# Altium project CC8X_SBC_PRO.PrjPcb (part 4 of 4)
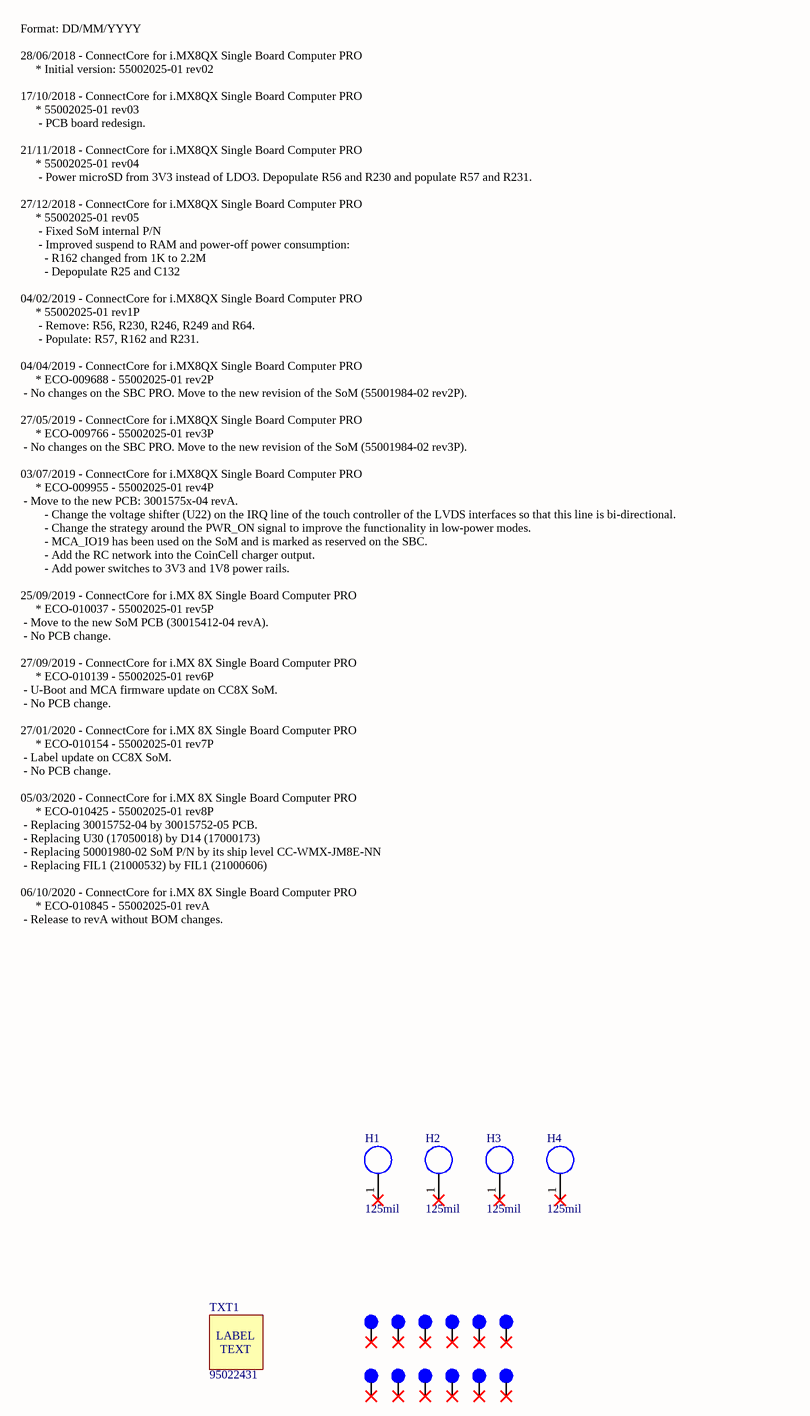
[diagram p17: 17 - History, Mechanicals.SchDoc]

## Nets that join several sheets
1V8_EXT: 02 - CCIMX8X Power, Control, MCA (R3.1 R5.1 R6.1), 03 - CCIMX8X Digital interfaces (R183.2 R184.2), 07 - Console, UART, CAN (C40.2 U10.7 U10.10), 08 - Ethernet1 (5 pins), 09 - Ethernet2 (R106.2 U9.5), 13 - Audio (R193.1 R194.1 R199.1 U21.S), 15 - Expansion connectors, User LEDs, RF signals (J20.4)
3V3_ETH: 08 - Ethernet1 (13 pins), 09 - Ethernet2 (7 pins)
3V3_EXT: 02 - CCIMX8X Power, Control, MCA (R2.1 R257.1), 03 - CCIMX8X Digital interfaces (R179.2 R180.2 R181.2 R182.2), 05 - Power, bootstrap, reset (J2.1 R40.1 R42.2), 06 - JTAG, SWD, MicroSD, Mini PCIe, MicroSIM (R29.1 R46.1 R57.2), 07 - Console, UART, CAN (15 pins), 08 - Ethernet1 (5 pins), 09 - Ethernet2 (R80.1), 10 - Displays and cameras (10 pins), 11 - USB HUB (R144.1 R145.1 R146.1 U24.S), 12 - USB Type C, USB microAB (8 pins), 13 - Audio (5 pins), 14 - I2C, XBee (L22.1 R171.2 R172.2 R196.2), 15 - Expansion connectors, User LEDs, RF signals (J27.1 R203.2 R204.2)
3V3_RF: 02 - CCIMX8X Power, Control, MCA (U1.F17 U1.F18), 04 - CCIMX8X RF, PCIe (R10.2), 15 - Expansion connectors, User LEDs, RF signals (J20.15)
5V: 05 - Power, bootstrap, reset (J3.1 R41.2), 07 - Console, UART, CAN (C145.2 C146.2 R245.1 R248.1), 10 - Displays and cameras (L8.1 L36.1), 15 - Expansion connectors, User LEDs, RF signals (J27.40)
GND: 02 - CCIMX8X Power, Control, MCA (179 pins), 05 - Power, bootstrap, reset (36 pins), 06 - JTAG, SWD, MicroSD, Mini PCIe, MicroSIM (68 pins), 07 - Console, UART, CAN (23 pins), 08 - Ethernet1 (37 pins), 09 - Ethernet2 (31 pins), 10 - Displays and cameras (17 pins), 11 - USB HUB (34 pins), 12 - USB Type C, USB microAB (38 pins), 13 - Audio (32 pins), 14 - I2C, XBee (6 pins), 15 - Expansion connectors, User LEDs, RF signals (8 pins)
LDO3: 02 - CCIMX8X Power, Control, MCA (R221.1), 06 - JTAG, SWD, MicroSD, Mini PCIe, MicroSIM (R56.2)
PCIe_VCC: 06 - JTAG, SWD, MicroSD, Mini PCIe, MicroSIM (26 pins), 14 - I2C, XBee (L23.1)
SHLD: 08 - Ethernet1 (J12.SHLD1 J12.SHLD2 R85.2), 09 - Ethernet2 (J13.SHLD1 J13.SHLD2), 11 - USB HUB (J18.SH1 J18.SH2 J18.SH3 J18.SH4), 12 - USB Type C, USB microAB (J28.6 J28.7 J28.8 J28.9)
VCC_LICELL: 02 - CCIMX8X Power, Control, MCA (D13.K), 05 - Power, bootstrap, reset (D4.1 R18.1), 15 - Expansion connectors, User LEDs, RF signals (J27.38)
VCC_MCA: 02 - CCIMX8X Power, Control, MCA (C162.2 R259.2 R260.2 U1.AM21), 05 - Power, bootstrap, reset (5 pins), 06 - JTAG, SWD, MicroSD, Mini PCIe, MicroSIM (CAD2.1 CAD2.5 J9.1), 15 - Expansion connectors, User LEDs, RF signals (J20.1)
VCC_SCU_1V8: 02 - CCIMX8X Power, Control, MCA (U1.AA29), 05 - Power, bootstrap, reset (R32.2 R35.2 R36.1 R38.1), 06 - JTAG, SWD, MicroSD, Mini PCIe, MicroSIM (CAD1.1 R14.1 R51.2)
VIN_PROT: 02 - CCIMX8X Power, Control, MCA (R1.1), 05 - Power, bootstrap, reset (13 pins), 06 - JTAG, SWD, MicroSD, Mini PCIe, MicroSIM (7 pins), 11 - USB HUB (C84.1 U14.7), 12 - USB Type C, USB microAB (8 pins), 14 - I2C, XBee (R190.1)
VLDO4_1V5: 02 - CCIMX8X Power, Control, MCA (R205.1), 06 - JTAG, SWD, MicroSD, Mini PCIe, MicroSIM (J7.6 J7.28 J7.48)
VSYS: 02 - CCIMX8X Power, Control, MCA (5 pins), 03 - CCIMX8X Digital interfaces (U1.B6)
5V_SBC_PWR_ON: 03 - CCIMX8X Digital interfaces (U1.E28), 05 - Power, bootstrap, reset (R40.2 U2.4)
ADC_IN0: 02 - CCIMX8X Power, Control, MCA (U1.K29), 15 - Expansion connectors, User LEDs, RF signals (J27.25)
ADC_IN1: 02 - CCIMX8X Power, Control, MCA (U1.L29), 15 - Expansion connectors, User LEDs, RF signals (J27.27)
ADC_IN4: 02 - CCIMX8X Power, Control, MCA (U1.AG25), 15 - Expansion connectors, User LEDs, RF signals (J27.26)
ADC_IN5: 02 - CCIMX8X Power, Control, MCA (U1.AG28), 15 - Expansion connectors, User LEDs, RF signals (J27.28)
AUD_I2C_SCL: 13 - Audio (U20.51), 14 - I2C, XBee (R175.2)
AUD_I2C_SDA: 13 - Audio (U20.52), 14 - I2C, XBee (R176.2)
AUD_INT#: 03 - CCIMX8X Digital interfaces (U1.AG15), 13 - Audio (R154.2 U20.56)
AUD_PWR_EN: 03 - CCIMX8X Digital interfaces (U1.E27), 13 - Audio (Q5.G Q6.G R168.2 R194.2)
BT_WAKEUP_HOST: 02 - CCIMX8X Power, Control, MCA (U1.AM25), 04 - CCIMX8X RF, PCIe (U1.G17), 15 - Expansion connectors, User LEDs, RF signals (J20.17)
BT_WAKEUP_SLAVE: 04 - CCIMX8X RF, PCIe (U1.G12), 15 - Expansion connectors, User LEDs, RF signals (J20.18)
CAN1_H: 07 - Console, UART, CAN (R60.2 U6.7), 15 - Expansion connectors, User LEDs, RF signals (J27.11)
CAN1_L: 07 - Console, UART, CAN (R60.1 U6.6), 15 - Expansion connectors, User LEDs, RF signals (J27.9)
CAN1_MODE: 03 - CCIMX8X Digital interfaces (U1.C17), 07 - Console, UART, CAN (R11.1), 15 - Expansion connectors, User LEDs, RF signals (J27.29)
CAN2_H: 07 - Console, UART, CAN (R62.2 U7.7), 15 - Expansion connectors, User LEDs, RF signals (J27.12)
CAN2_L: 07 - Console, UART, CAN (R62.1 U7.6), 15 - Expansion connectors, User LEDs, RF signals (J27.10)
CAN2_MODE: 03 - CCIMX8X Digital interfaces (U1.C18), 07 - Console, UART, CAN (R233.1), 15 - Expansion connectors, User LEDs, RF signals (J27.31)
CAN/RS485#: 03 - CCIMX8X Digital interfaces (U1.AG13), 07 - Console, UART, CAN (R163.1 U4.6 U5.6)
CONSOLE_RX: 03 - CCIMX8X Digital interfaces (U1.V29), 07 - Console, UART, CAN (D6.2 J11.2)
CONSOLE_TX: 03 - CCIMX8X Digital interfaces (U1.W29), 07 - Console, UART, CAN (D7.2 J11.1)
CSI_D00: 03 - CCIMX8X Digital interfaces (U1.AH25), 10 - Displays and cameras (J17.2)
CSI_D01: 03 - CCIMX8X Digital interfaces (U1.AH26), 10 - Displays and cameras (J17.3)
CSI_D02: 03 - CCIMX8X Digital interfaces (U1.AJ25), 10 - Displays and cameras (J17.4)
CSI_D03: 03 - CCIMX8X Digital interfaces (U1.AH24), 10 - Displays and cameras (J17.5)
CSI_D04: 03 - CCIMX8X Digital interfaces (U1.AJ23), 10 - Displays and cameras (J17.6)
CSI_D05: 03 - CCIMX8X Digital interfaces (U1.AJ24), 10 - Displays and cameras (J17.7)
CSI_D06: 03 - CCIMX8X Digital interfaces (U1.AH20), 10 - Displays and cameras (J17.8)
CSI_D07: 03 - CCIMX8X Digital interfaces (U1.AJ22), 10 - Displays and cameras (J17.9)
CSI_EN: 03 - CCIMX8X Digital interfaces (U1.AK27), 10 - Displays and cameras (J17.15)
CSI_HSYNC: 03 - CCIMX8X Digital interfaces (U1.AK28), 10 - Displays and cameras (J17.13)
CSI_MCLK: 03 - CCIMX8X Digital interfaces (U1.AJ21), 10 - Displays and cameras (J17.11)
CSI_PCLK: 03 - CCIMX8X Digital interfaces (U1.AH22), 10 - Displays and cameras (J17.12)
CSI_RESET: 03 - CCIMX8X Digital interfaces (U1.AK26), 10 - Displays and cameras (J17.16)
CSI_SCL: 10 - Displays and cameras (J17.18), 14 - I2C, XBee (R185.2)
CSI_SDA: 10 - Displays and cameras (J17.19), 14 - I2C, XBee (R186.2)
CSI_VSYNC: 03 - CCIMX8X Digital interfaces (U1.AH23), 10 - Displays and cameras (J17.14)
ENET_PWR: 03 - CCIMX8X Digital interfaces (U1.AN4), 08 - Ethernet1 (Q2.G R69.2)
EXP_I2C_GPIO: 03 - CCIMX8X Digital interfaces (U1.AN5), 15 - Expansion connectors, User LEDs, RF signals (J27.16)
EXP_I2C_IRQ_N: 03 - CCIMX8X Digital interfaces (U1.AF1), 15 - Expansion connectors, User LEDs, RF signals (J27.14)
EXP_I2C_SCL: 14 - I2C, XBee (R187.2), 15 - Expansion connectors, User LEDs, RF signals (J27.13)
EXP_I2C_SDA: 14 - I2C, XBee (R188.2), 15 - Expansion connectors, User LEDs, RF signals (J27.15)
EXPANSION_USB1_D_N: 11 - USB HUB (R192.2), 15 - Expansion connectors, User LEDs, RF signals (J27.34)
EXPANSION_USB1_D_P: 11 - USB HUB (R191.2), 15 - Expansion connectors, User LEDs, RF signals (J27.32)
EXPANSION_USB2_D_N: 11 - USB HUB (R79.2), 15 - Expansion connectors, User LEDs, RF signals (J27.35)
EXPANSION_USB2_D_P: 11 - USB HUB (R78.2), 15 - Expansion connectors, User LEDs, RF signals (J27.33)
FLEXCAN1_RX: 03 - CCIMX8X Digital interfaces (U1.R29), 07 - Console, UART, CAN (U6.4)
FLEXCAN1_TX: 03 - CCIMX8X Digital interfaces (U1.P29), 07 - Console, UART, CAN (U6.1)
FLEXCAN2_RX/UART3_RX: 03 - CCIMX8X Digital interfaces (U1.U29), 07 - Console, UART, CAN (U4.4)
FLEXCAN2_TX/UART3_TX: 03 - CCIMX8X Digital interfaces (U1.T29), 07 - Console, UART, CAN (U5.4)
GPIO0_12: 03 - CCIMX8X Digital interfaces (U1.D25), 15 - Expansion connectors, User LEDs, RF signals (J27.36)
GPIO4_19: 03 - CCIMX8X Digital interfaces (U1.E4), 15 - Expansion connectors, User LEDs, RF signals (J27.30)
GPIO4_20: 03 - CCIMX8X Digital interfaces (U1.E3), 15 - Expansion connectors, User LEDs, RF signals (J20.13)
GPIO4_21: 03 - CCIMX8X Digital interfaces (U1.F3), 15 - Expansion connectors, User LEDs, RF signals (J20.14)
GPIO5_09: 03 - CCIMX8X Digital interfaces (U1.A12), 15 - Expansion connectors, User LEDs, RF signals (J27.37)
GPS_COEX: 04 - CCIMX8X RF, PCIe (U1.E9), 15 - Expansion connectors, User LEDs, RF signals (J20.23)
I2C3_SCL: 03 - CCIMX8X Digital interfaces (U1.F28), 14 - I2C, XBee (6 pins)
I2C3_SDA: 03 - CCIMX8X Digital interfaces (U1.E29), 14 - I2C, XBee (6 pins)
IMX8_ON_OFF: 02 - CCIMX8X Power, Control, MCA (U1.AG18), 05 - Power, bootstrap, reset (R213.2)
JTAG_TCK: 02 - CCIMX8X Power, Control, MCA (U1.AG20), 06 - JTAG, SWD, MicroSD, Mini PCIe, MicroSIM (CAD1.4)
JTAG_TDI: 02 - CCIMX8X Power, Control, MCA (U1.AH27), 06 - JTAG, SWD, MicroSD, Mini PCIe, MicroSIM (CAD1.8)
JTAG_TDO: 02 - CCIMX8X Power, Control, MCA (U1.AG21), 06 - JTAG, SWD, MicroSD, Mini PCIe, MicroSIM (CAD1.6)
JTAG_TMS: 02 - CCIMX8X Power, Control, MCA (U1.AH28), 06 - JTAG, SWD, MicroSD, Mini PCIe, MicroSIM (CAD1.2)
JTAG_TRST_GPIO: 02 - CCIMX8X Power, Control, MCA (U1.AG19), 06 - JTAG, SWD, MicroSD, Mini PCIe, MicroSIM (CAD1.9 R51.1)
LINE1_IN_L: 13 - Audio (L19.1), 15 - Expansion connectors, User LEDs, RF signals (J20.29)
LINE1_IN_R: 13 - Audio (L18.1), 15 - Expansion connectors, User LEDs, RF signals (J20.27)
LINE2_IN_L: 13 - Audio (L21.1), 15 - Expansion connectors, User LEDs, RF signals (J20.33)
LINE2_IN_R: 13 - Audio (L20.1), 15 - Expansion connectors, User LEDs, RF signals (J20.31)
LINE_OUT_L: 13 - Audio (U20.24), 15 - Expansion connectors, User LEDs, RF signals (J20.37)
LINE_OUT_R: 13 - Audio (U20.23), 15 - Expansion connectors, User LEDs, RF signals (J20.35)
LTE_PRI: 04 - CCIMX8X RF, PCIe (U1.E10), 15 - Expansion connectors, User LEDs, RF signals (J20.24)
LTE_SYNC: 04 - CCIMX8X RF, PCIe (U1.E11), 15 - Expansion connectors, User LEDs, RF signals (J20.26)
M40_UART_RX: 07 - Console, UART, CAN (R66.1 R68.1), 15 - Expansion connectors, User LEDs, RF signals (J27.23)
M40_UART_RX_1V8: 02 - CCIMX8X Power, Control, MCA (U1.AG27), 07 - Console, UART, CAN (R68.2 U10.9)
M40_UART_TX: 07 - Console, UART, CAN (R65.1 R67.1), 15 - Expansion connectors, User LEDs, RF signals (J27.21)
M40_UART_TX_1V8: 02 - CCIMX8X Power, Control, MCA (U1.AG26), 07 - Console, UART, CAN (R67.2 U10.8)
MCA_CLKOUT32K: 02 - CCIMX8X Power, Control, MCA (U1.AL21), 15 - Expansion connectors, User LEDs, RF signals (J20.3)
MCA_IO5: 02 - CCIMX8X Power, Control, MCA (R259.1 U1.AL28 U32.4), 15 - Expansion connectors, User LEDs, RF signals (J20.10)
MCA_IO6: 02 - CCIMX8X Power, Control, MCA (R260.1 U1.AK29 U33.4), 15 - Expansion connectors, User LEDs, RF signals (J20.5)
MCA_IO7: 02 - CCIMX8X Power, Control, MCA (U1.AJ29), 15 - Expansion connectors, User LEDs, RF signals (J20.6)
MCA_IO8: 02 - CCIMX8X Power, Control, MCA (U1.AH29), 15 - Expansion connectors, User LEDs, RF signals (J20.7)
MCA_IO9: 02 - CCIMX8X Power, Control, MCA (U1.AG29), 05 - Power, bootstrap, reset (R255.2), 15 - Expansion connectors, User LEDs, RF signals (J20.8)
MCA_IO14: 02 - CCIMX8X Power, Control, MCA (U1.AL26), 15 - Expansion connectors, User LEDs, RF signals (J20.11)
MCA_IO17: 02 - CCIMX8X Power, Control, MCA (U1.AL23), 15 - Expansion connectors, User LEDs, RF signals (J20.16)
MCA_UART2_CTS: 02 - CCIMX8X Power, Control, MCA (U1.AN23), 14 - I2C, XBee (J23.9)
MCA_UART2_RTS: 02 - CCIMX8X Power, Control, MCA (U1.AL27), 14 - I2C, XBee (J23.5 R198.2)
MCA_UART2_RX: 02 - CCIMX8X Power, Control, MCA (U1.AN22), 14 - I2C, XBee (J22.2)
MCA_UART2_TX: 02 - CCIMX8X Power, Control, MCA (U1.AN21), 14 - I2C, XBee (J22.3)
MCA_VIN_DET: 02 - CCIMX8X Power, Control, MCA (U1.AM27), 05 - Power, bootstrap, reset (R28.2)
MCA_VREF_OUT: 02 - CCIMX8X Power, Control, MCA (U1.AM24), 15 - Expansion connectors, User LEDs, RF signals (J20.12)
MCLK_OUT0: 03 - CCIMX8X Digital interfaces (U1.B24), 13 - Audio (U20.5)
MIC_N: 13 - Audio (L17.1), 15 - Expansion connectors, User LEDs, RF signals (J20.28)
MIC_P: 13 - Audio (L16.1), 15 - Expansion connectors, User LEDs, RF signals (J20.30)
MIPI_CSI0_CLK_N: 03 - CCIMX8X Digital interfaces (U1.AM14), 10 - Displays and cameras (J15.8)
MIPI_CSI0_CLK_P: 03 - CCIMX8X Digital interfaces (U1.AM13), 10 - Displays and cameras (J15.7)
MIPI_CSI0_DATA0_N: 03 - CCIMX8X Digital interfaces (U1.AL16), 10 - Displays and cameras (J15.14)
MIPI_CSI0_DATA0_P: 03 - CCIMX8X Digital interfaces (U1.AL15), 10 - Displays and cameras (J15.13)
MIPI_CSI0_DATA1_N: 03 - CCIMX8X Digital interfaces (U1.AL13), 10 - Displays and cameras (J15.11)
MIPI_CSI0_DATA1_P: 03 - CCIMX8X Digital interfaces (U1.AL12), 10 - Displays and cameras (J15.10)
MIPI_CSI0_I2C0_SCL: 03 - CCIMX8X Digital interfaces (R184.1 U1.AK25), 10 - Displays and cameras (J15.3)
MIPI_CSI0_I2C0_SDA: 03 - CCIMX8X Digital interfaces (R183.1 U1.AK24), 10 - Displays and cameras (J15.2)
MIPI_CSI0_RESET_N: 03 - CCIMX8X Digital interfaces (U1.AG8), 10 - Displays and cameras (J15.5)
MIPI_DSI0_CLK_N: 03 - CCIMX8X Digital interfaces (U1.AN6), 10 - Displays and cameras (L27.1)
MIPI_DSI0_CLK_P: 03 - CCIMX8X Digital interfaces (U1.AN7), 10 - Displays and cameras (L27.4)
MIPI_DSI0_DATA0_N: 03 - CCIMX8X Digital interfaces (U1.AN9), 10 - Displays and cameras (L24.1)
MIPI_DSI0_DATA0_P: 03 - CCIMX8X Digital interfaces (U1.AN10), 10 - Displays and cameras (L24.4)
MIPI_DSI0_DATA1_N: 03 - CCIMX8X Digital interfaces (U1.AN12), 10 - Displays and cameras (L25.1)
MIPI_DSI0_DATA1_P: 03 - CCIMX8X Digital interfaces (U1.AN13), 10 - Displays and cameras (L25.4)
MIPI_DSI0_DATA2_N: 03 - CCIMX8X Digital interfaces (U1.AN15), 10 - Displays and cameras (L26.1)
MIPI_DSI0_DATA2_P: 03 - CCIMX8X Digital interfaces (U1.AN16), 10 - Displays and cameras (L26.4)
MIPI_DSI0_DATA3_N: 03 - CCIMX8X Digital interfaces (U1.AN18), 10 - Displays and cameras (L28.1)
MIPI_DSI0_DATA3_P: 03 - CCIMX8X Digital interfaces (U1.AN19), 10 - Displays and cameras (L28.4)
MIPI_DSI0_I2C0_SCL: 03 - CCIMX8X Digital interfaces (R180.1 U1.V1), 10 - Displays and cameras (J14.17)
MIPI_DSI0_I2C0_SDA: 03 - CCIMX8X Digital interfaces (R179.1 U1.W1), 10 - Displays and cameras (J14.18)
MIPI_DSI0_IRQ_N: 03 - CCIMX8X Digital interfaces (U1.AG14), 10 - Displays and cameras (R251.2 R252.1 U22.1)
MIPI_DSI0_PWM0_OUT: 03 - CCIMX8X Digital interfaces (U1.Y1), 10 - Displays and cameras (J14.16)
MIPI_DSI1_CLK_N: 03 - CCIMX8X Digital interfaces (U1.AJ19), 10 - Displays and cameras (L34.1)
MIPI_DSI1_CLK_P: 03 - CCIMX8X Digital interfaces (U1.AJ18), 10 - Displays and cameras (L34.4)
MIPI_DSI1_DATA0_N: 03 - CCIMX8X Digital interfaces (U1.AJ15), 10 - Displays and cameras (L31.1)
MIPI_DSI1_DATA0_P: 03 - CCIMX8X Digital interfaces (U1.AJ16), 10 - Displays and cameras (L31.4)
MIPI_DSI1_DATA1_N: 03 - CCIMX8X Digital interfaces (U1.AK15), 10 - Displays and cameras (L32.1)
MIPI_DSI1_DATA1_P: 03 - CCIMX8X Digital interfaces (U1.AK16), 10 - Displays and cameras (L32.4)
MIPI_DSI1_DATA2_N: 03 - CCIMX8X Digital interfaces (U1.AH16), 10 - Displays and cameras (L33.1)
MIPI_DSI1_DATA2_P: 03 - CCIMX8X Digital interfaces (U1.AH15), 10 - Displays and cameras (L33.4)
MIPI_DSI1_DATA3_N: 03 - CCIMX8X Digital interfaces (U1.AK19), 10 - Displays and cameras (L35.1)
MIPI_DSI1_DATA3_P: 03 - CCIMX8X Digital interfaces (U1.AK18), 10 - Displays and cameras (L35.4)
MIPI_DSI1_I2C0_SCL: 03 - CCIMX8X Digital interfaces (R182.1 U1.AB1), 10 - Displays and cameras (J16.17)
MIPI_DSI1_I2C0_SDA: 03 - CCIMX8X Digital interfaces (R181.1 U1.AC1), 10 - Displays and cameras (J16.18)
MIPI_DSI1_IRQ_N: 03 - CCIMX8X Digital interfaces (U1.AG9), 10 - Displays and cameras (R253.2 R254.1 U22.4)
MIPI_DSI1_PWM0_OUT: 03 - CCIMX8X Digital interfaces (U1.AD1), 10 - Displays and cameras (J16.16)
PCIE_DIS_N: 03 - CCIMX8X Digital interfaces (U1.E24), 06 - JTAG, SWD, MicroSD, Mini PCIe, MicroSIM (J7.20)
PCIE_I2C_SCL: 06 - JTAG, SWD, MicroSD, Mini PCIe, MicroSIM (J7.30), 14 - I2C, XBee (R177.2)
PCIE_I2C_SDA: 06 - JTAG, SWD, MicroSD, Mini PCIe, MicroSIM (J7.32), 14 - I2C, XBee (R178.2)
PCIE_RESET_N: 03 - CCIMX8X Digital interfaces (U1.AG1), 06 - JTAG, SWD, MicroSD, Mini PCIe, MicroSIM (J7.22)
PCIE_RX_N: 04 - CCIMX8X RF, PCIe (R227.1), 06 - JTAG, SWD, MicroSD, Mini PCIe, MicroSIM (J7.23)
PCIE_RX_P: 04 - CCIMX8X RF, PCIe (R226.1), 06 - JTAG, SWD, MicroSD, Mini PCIe, MicroSIM (J7.25)
PCIE_SOM_CLK_N: 04 - CCIMX8X RF, PCIe (R223.1), 06 - JTAG, SWD, MicroSD, Mini PCIe, MicroSIM (R111.2 R117.1)
PCIE_SOM_CLK_P: 04 - CCIMX8X RF, PCIe (R222.1), 06 - JTAG, SWD, MicroSD, Mini PCIe, MicroSIM (R30.1 R110.2)
PCIE_TX_N: 04 - CCIMX8X RF, PCIe (C138.1), 06 - JTAG, SWD, MicroSD, Mini PCIe, MicroSIM (J7.31)
PCIE_TX_P: 04 - CCIMX8X RF, PCIe (C137.1), 06 - JTAG, SWD, MicroSD, Mini PCIe, MicroSIM (J7.33)
PCIE_VCC_EN: 03 - CCIMX8X Digital interfaces (U1.E25), 06 - JTAG, SWD, MicroSD, Mini PCIe, MicroSIM (R45.1)
PCIE_WAKE_N: 03 - CCIMX8X Digital interfaces (U1.D19), 06 - JTAG, SWD, MicroSD, Mini PCIe, MicroSIM (J7.1 R52.1)
PCM_CLK: 04 - CCIMX8X RF, PCIe (U1.G13), 13 - Audio (R155.1), 15 - Expansion connectors, User LEDs, RF signals (J20.19)
PCM_IN: 04 - CCIMX8X RF, PCIe (U1.G14), 13 - Audio (R158.1), 15 - Expansion connectors, User LEDs, RF signals (J20.20)
PCM_OUT: 04 - CCIMX8X RF, PCIe (U1.F13), 13 - Audio (R157.1), 15 - Expansion connectors, User LEDs, RF signals (J20.21)
PCM_SYNC: 04 - CCIMX8X RF, PCIe (U1.F14), 13 - Audio (R156.1), 15 - Expansion connectors, User LEDs, RF signals (J20.22)
POR_B: 02 - CCIMX8X Power, Control, MCA (U1.AH10), 06 - JTAG, SWD, MicroSD, Mini PCIe, MicroSIM (CAD1.10)
POWER_BUTTON: 05 - Power, bootstrap, reset (R13.1 R213.1 SW1.3 SW1.4), 15 - Expansion connectors, User LEDs, RF signals (J20.40)
POWER_LED: 02 - CCIMX8X Power, Control, MCA (U1.AL22), 05 - Power, bootstrap, reset (Q8.G R216.1)
PWR_ON: 02 - CCIMX8X Power, Control, MCA (U1.AJ12), 05 - Power, bootstrap, reset (R64.2)
QOW: 04 - CCIMX8X RF, PCIe (U1.F23), 15 - Expansion connectors, User LEDs, RF signals (J20.25)
RF_KILL: 03 - CCIMX8X Digital interfaces (U1.G29), 04 - CCIMX8X RF, PCIe (R10.1 U1.B16 U1.B17)
RGMII1_INT_ B: 03 - CCIMX8X Digital interfaces (U1.AA1), 08 - Ethernet1 (R16.2 U9.6)
RGMII1_RD0: 03 - CCIMX8X Digital interfaces (U1.A16), 08 - Ethernet1 (R86.1 R87.2 U11.31)
RGMII1_RD1: 03 - CCIMX8X Digital interfaces (U1.A15), 08 - Ethernet1 (R88.1 R89.2 U11.30)
RGMII1_RD2: 03 - CCIMX8X Digital interfaces (U1.A14), 08 - Ethernet1 (R94.1 R95.2 U11.28)
RGMII1_RD3: 03 - CCIMX8X Digital interfaces (U1.A13), 08 - Ethernet1 (R98.1 R99.2 U11.27)
RGMII1_RESET_N: 03 - CCIMX8X Digital interfaces (U1.AG11), 08 - Ethernet1 (U11.2)
RGMII1_RX_CTL: 03 - CCIMX8X Digital interfaces (U1.A17), 08 - Ethernet1 (R92.1 R93.2 U11.32)
RGMII1_RXC: 03 - CCIMX8X Digital interfaces (U1.A18), 08 - Ethernet1 (R96.1 R97.2 U11.33)
RGMII1_TD0: 03 - CCIMX8X Digital interfaces (U1.A22), 08 - Ethernet1 (U11.36)
RGMII1_TD1: 03 - CCIMX8X Digital interfaces (U1.A21), 08 - Ethernet1 (U11.37)
RGMII1_TD2: 03 - CCIMX8X Digital interfaces (U1.A20), 08 - Ethernet1 (U11.38)
RGMII1_TD3: 03 - CCIMX8X Digital interfaces (U1.A19), 08 - Ethernet1 (U11.39)
RGMII1_TX_CTL: 03 - CCIMX8X Digital interfaces (U1.A23), 08 - Ethernet1 (U11.34)
RGMII1_TXC: 03 - CCIMX8X Digital interfaces (U1.A24), 08 - Ethernet1 (U11.35)
RGMII2_INT_ B: 03 - CCIMX8X Digital interfaces (U1.AE1), 09 - Ethernet2 (R80.2 U9.3)
RGMII2_RD0: 03 - CCIMX8X Digital interfaces (U1.D21), 09 - Ethernet2 (R118.1 R119.2 U12.31)
RGMII2_RD1: 03 - CCIMX8X Digital interfaces (U1.D23), 09 - Ethernet2 (R120.1 R121.2 U12.30)
RGMII2_RD2: 03 - CCIMX8X Digital interfaces (U1.C20), 09 - Ethernet2 (R126.1 R127.2 U12.28)
RGMII2_RD3: 03 - CCIMX8X Digital interfaces (U1.B22), 09 - Ethernet2 (R130.1 R131.2 U12.27)
RGMII2_RESET_N: 03 - CCIMX8X Digital interfaces (U1.AG12), 09 - Ethernet2 (U12.2)
RGMII2_RX_CTL: 03 - CCIMX8X Digital interfaces (U1.C23), 09 - Ethernet2 (R124.1 R125.2 U12.32)
RGMII2_RXC: 03 - CCIMX8X Digital interfaces (U1.D22), 09 - Ethernet2 (R128.1 R129.2 U12.33)
RGMII2_TD0: 03 - CCIMX8X Digital interfaces (U1.C22), 09 - Ethernet2 (U12.36)
RGMII2_TD1: 03 - CCIMX8X Digital interfaces (U1.D20), 09 - Ethernet2 (U12.37)
RGMII2_TD2: 03 - CCIMX8X Digital interfaces (U1.C21), 09 - Ethernet2 (U12.38)
RGMII2_TD3: 03 - CCIMX8X Digital interfaces (U1.B21), 09 - Ethernet2 (U12.39)
RGMII2_TX_CTL: 03 - CCIMX8X Digital interfaces (U1.B19), 09 - Ethernet2 (U12.34)
RGMII2_TXC: 03 - CCIMX8X Digital interfaces (U1.B20), 09 - Ethernet2 (U12.35)
RGMII_MDC: 03 - CCIMX8X Digital interfaces (U1.A10), 08 - Ethernet1 (U29.5)
RGMII_MDC_3V3: 08 - Ethernet1 (R72.1 U11.1 U29.8), 09 - Ethernet2 (R104.1 U12.1)
RGMII_MDIO: 03 - CCIMX8X Digital interfaces (U1.A11), 08 - Ethernet1 (U29.4)
RGMII_MDIO_3V3: 08 - Ethernet1 (R73.1 U11.48 U29.1), 09 - Ethernet2 (R105.1 U12.48)
RS485_A: 07 - Console, UART, CAN (R63.1 U8.6), 15 - Expansion connectors, User LEDs, RF signals (J27.22)
RS485_B: 07 - Console, UART, CAN (R63.2 U8.7), 15 - Expansion connectors, User LEDs, RF signals (J27.24)
RS485_RE#/DE: 03 - CCIMX8X Digital interfaces (U1.AG10), 07 - Console, UART, CAN (U8.2 U8.3)
SAI0_RXD: 03 - CCIMX8X Digital interfaces (U1.E21), 13 - Audio (U20.7)
SAI0_TXC: 03 - CCIMX8X Digital interfaces (U1.E23), 13 - Audio (U20.8)
SAI0_TXD: 03 - CCIMX8X Digital interfaces (U1.E20), 13 - Audio (U20.9)
SAI0_TXFS: 03 - CCIMX8X Digital interfaces (U1.C19), 13 - Audio (U20.10)
SCU_BOOT_MODE0: 02 - CCIMX8X Power, Control, MCA (U1.AE29), 05 - Power, bootstrap, reset (R33.2 S2.2 TP14.1)
SCU_BOOT_MODE1: 02 - CCIMX8X Power, Control, MCA (U1.AD29), 05 - Power, bootstrap, reset (R32.1 S2.1 TP13.1)
SCU_BOOT_MODE2: 02 - CCIMX8X Power, Control, MCA (U1.AJ28), 05 - Power, bootstrap, reset (R36.2 R37.2)
SCU_BOOT_MODE3: 02 - CCIMX8X Power, Control, MCA (U1.AJ27), 05 - Power, bootstrap, reset (R38.2 R39.2)
SPI0_CS0: 03 - CCIMX8X Digital interfaces (U1.E19), 15 - Expansion connectors, User LEDs, RF signals (J27.4)
SPI0_CS1: 03 - CCIMX8X Digital interfaces (U1.E26), 15 - Expansion connectors, User LEDs, RF signals (J27.6)
SPI0_IRQ_N: 03 - CCIMX8X Digital interfaces (U1.D18), 15 - Expansion connectors, User LEDs, RF signals (J27.8)
SPI0_SCK: 03 - CCIMX8X Digital interfaces (U1.D17), 15 - Expansion connectors, User LEDs, RF signals (J27.3)
SPI0_SDI: 03 - CCIMX8X Digital interfaces (U1.E22), 15 - Expansion connectors, User LEDs, RF signals (J27.5)
SPI0_SDO: 03 - CCIMX8X Digital interfaces (U1.E18), 15 - Expansion connectors, User LEDs, RF signals (J27.7)
SPKL_N: 13 - Audio (U20.22), 15 - Expansion connectors, User LEDs, RF signals (J20.34)
SPKL_P: 13 - Audio (U20.20), 15 - Expansion connectors, User LEDs, RF signals (J20.32)
SPKR_N: 13 - Audio (U20.15), 15 - Expansion connectors, User LEDs, RF signals (J20.38)
SPKR_P: 13 - Audio (U20.17), 15 - Expansion connectors, User LEDs, RF signals (J20.36)
SWD_CLK/PWR_IO: 02 - CCIMX8X Power, Control, MCA (U1.AN24), 05 - Power, bootstrap, reset (R13.2 R15.1), 06 - JTAG, SWD, MicroSD, Mini PCIe, MicroSIM (CAD2.4 J9.4)
SWD_DIO: 02 - CCIMX8X Power, Control, MCA (U1.AN26), 06 - JTAG, SWD, MicroSD, Mini PCIe, MicroSIM (CAD2.2 J9.2)
SYS_RESET: 02 - CCIMX8X Power, Control, MCA (U1.AN25), 05 - Power, bootstrap, reset (R17.1 SW2.3 SW2.4), 06 - JTAG, SWD, MicroSD, Mini PCIe, MicroSIM (CAD2.10 J9.10), 15 - Expansion connectors, User LEDs, RF signals (J20.39)
UART0_CTS_B: 03 - CCIMX8X Digital interfaces (U1.M29), 15 - Expansion connectors, User LEDs, RF signals (J27.20)
UART0_RTS_B: 03 - CCIMX8X Digital interfaces (U1.N29), 15 - Expansion connectors, User LEDs, RF signals (J27.18)
UART0_RX: 03 - CCIMX8X Digital interfaces (U1.R1), 15 - Expansion connectors, User LEDs, RF signals (J27.19)
UART0_TX: 03 - CCIMX8X Digital interfaces (U1.P1), 15 - Expansion connectors, User LEDs, RF signals (J27.17)
USB_HUB_RESET_N: 03 - CCIMX8X Digital interfaces (U1.E17), 11 - USB HUB (C83.2 R12.2 R137.1 U13.26)
USB_OTG1_N: 03 - CCIMX8X Digital interfaces (TP16.1 U1.A6), 11 - USB HUB (R242.2 U13.30), 14 - I2C, XBee (R240.1)
USB_OTG1_P: 03 - CCIMX8X Digital interfaces (TP15.1 U1.A7), 11 - USB HUB (R243.2 U13.31), 14 - I2C, XBee (R241.1)
USB_OTG2_ID: 03 - CCIMX8X Digital interfaces (U1.C10), 12 - USB Type C, USB microAB (J28.4)
USB_OTG2_N: 03 - CCIMX8X Digital interfaces (U1.A8), 11 - USB HUB (R238.2), 12 - USB Type C, USB microAB (5 pins)
USB_OTG2_P: 03 - CCIMX8X Digital interfaces (U1.A9), 11 - USB HUB (R239.2), 12 - USB Type C, USB microAB (5 pins)
USB_PCIe_D_N: 06 - JTAG, SWD, MicroSD, Mini PCIe, MicroSIM (J7.36), 11 - USB HUB (R229.2)
USB_PCIe_D_P: 06 - JTAG, SWD, MicroSD, Mini PCIe, MicroSIM (J7.38), 11 - USB HUB (R228.2)
USB_PWR: 03 - CCIMX8X Digital interfaces (U1.C24), 11 - USB HUB (Q3.G R144.2)
USB_SS3_ALERT_N: 03 - CCIMX8X Digital interfaces (U1.C7), 12 - USB Type C, USB microAB (R147.2 U18.10)
USB_SS3_BUS_SEL: 03 - CCIMX8X Digital interfaces (U1.C11), 12 - USB Type C, USB microAB (U17.12)
USB_SS3_INT_B: 03 - CCIMX8X Digital interfaces (U1.C8), 12 - USB Type C, USB microAB (U18.9 U31.1)
USB_SS3_RX_N: 03 - CCIMX8X Digital interfaces (U1.B12), 12 - USB Type C, USB microAB (U17.14)
USB_SS3_RX_P: 03 - CCIMX8X Digital interfaces (U1.B13), 12 - USB Type C, USB microAB (U17.13)
USB_SS3_SCL: 12 - USB Type C, USB microAB (U18.8), 14 - I2C, XBee (R173.2)
USB_SS3_SDA: 12 - USB Type C, USB microAB (U18.7), 14 - I2C, XBee (R174.2)
USB_SS3_SW_PWR: 03 - CCIMX8X Digital interfaces (U1.C9), 12 - USB Type C, USB microAB (R235.1 U17.3 U31.2)
USB_SS3_TX_N: 03 - CCIMX8X Digital interfaces (U1.B9), 12 - USB Type C, USB microAB (U17.9)
USB_SS3_TX_P: 03 - CCIMX8X Digital interfaces (U1.B10), 12 - USB Type C, USB microAB (U17.10)
USDHC1_CD_B: 03 - CCIMX8X Digital interfaces (U1.G2), 06 - JTAG, SWD, MicroSD, Mini PCIe, MicroSIM (J10.9 J10.10 R54.2)
USDHC1_CLK: 03 - CCIMX8X Digital interfaces (U1.L1), 06 - JTAG, SWD, MicroSD, Mini PCIe, MicroSIM (R58.1)
USDHC1_CMD: 03 - CCIMX8X Digital interfaces (U1.F1), 06 - JTAG, SWD, MicroSD, Mini PCIe, MicroSIM (J10.3 R53.1)
USDHC1_DATA0: 03 - CCIMX8X Digital interfaces (U1.G1), 06 - JTAG, SWD, MicroSD, Mini PCIe, MicroSIM (J10.7 R55.1)
USDHC1_DATA1: 03 - CCIMX8X Digital interfaces (U1.H1), 06 - JTAG, SWD, MicroSD, Mini PCIe, MicroSIM (J10.8)
USDHC1_DATA2: 03 - CCIMX8X Digital interfaces (U1.J1), 06 - JTAG, SWD, MicroSD, Mini PCIe, MicroSIM (J10.1)
USDHC1_DATA3: 03 - CCIMX8X Digital interfaces (U1.K1), 06 - JTAG, SWD, MicroSD, Mini PCIe, MicroSIM (J10.2)
USER_LED0: 02 - CCIMX8X Power, Control, MCA (U1.AM23), 15 - Expansion connectors, User LEDs, RF signals (Q14.G R108.1)
USER_LED1: 02 - CCIMX8X Power, Control, MCA (U1.AF29), 15 - Expansion connectors, User LEDs, RF signals (Q13.G R109.1)
VLDO2_VSELECT: 02 - CCIMX8X Power, Control, MCA (U1.AH13), 03 - CCIMX8X Digital interfaces (R232.1)
XBEE_D_N: 11 - USB HUB (R77.2), 14 - I2C, XBee (J22.8 R240.2)
XBEE_D_P: 11 - USB HUB (R76.2), 14 - I2C, XBee (J22.7 R241.2)
XBEE_ON/SLEEP_N: 02 - CCIMX8X Power, Control, MCA (U1.AL24), 14 - I2C, XBee (J23.8)
XBEE_RESET_N: 02 - CCIMX8X Power, Control, MCA (U1.AL25), 14 - I2C, XBee (J22.5)
XBEE_SLEEP_RQ: 02 - CCIMX8X Power, Control, MCA (U1.AM26), 14 - I2C, XBee (J22.9)

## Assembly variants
55002025-01: not fitted C5 C10 C31 C32 C37 C39 C40 C46 C64 C132 C137 C138 C139 C140 C142 C147 C148 C149 D1 D2 J20 J27 J28 L23 L37 L38 L39 R12 R14 R22 R25 R29 R30 R36 R38 R43 R56 R64 R65 R66 R71 R72 R78 R79 R87 R88 R90 R92 R94 R96 R98 R100 R102 R103 R104 R110 R111 R112 R117 R118 R120 R122 R124 R126 R128 R130 R132 R134 R135 R146 R170 R177 R178 R189 R190 R191 R192 R195 R196 R197 R198 R199 R213 R215 R217 R218 R222 R223 R224 R225 R226 R227 R230 R234 R235 R236 R237 R238 R239 R240 R241 R242 R243 R246 R249 R252 R254 R256 U10 U28 U31
55002025-99: not fitted C5 C10 C31 C32 C37 C39 C40 C46 C64 C132 C137 C138 C139 C140 C142 C147 C148 C149 D1 D2 J20 J27 J28 L23 L37 L38 L39 R12 R14 R22 R25 R29 R30 R36 R38 R43 R56 R64 R65 R66 R71 R72 R78 R79 R87 R88 R90 R92 R94 R96 R98 R100 R102 R103 R104 R110 R111 R112 R117 R118 R120 R122 R124 R126 R128 R130 R132 R134 R135 R146 R170 R177 R178 R189 R190 R191 R192 R195 R196 R197 R198 R199 R213 R215 R217 R218 R222 R223 R224 R225 R226 R227 R230 R234 R235 R236 R237 R238 R239 R240 R241 R242 R243 R246 R249 R252 R254 R256 U10 U28 U31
